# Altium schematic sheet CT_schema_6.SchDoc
size 266 x 267 mm
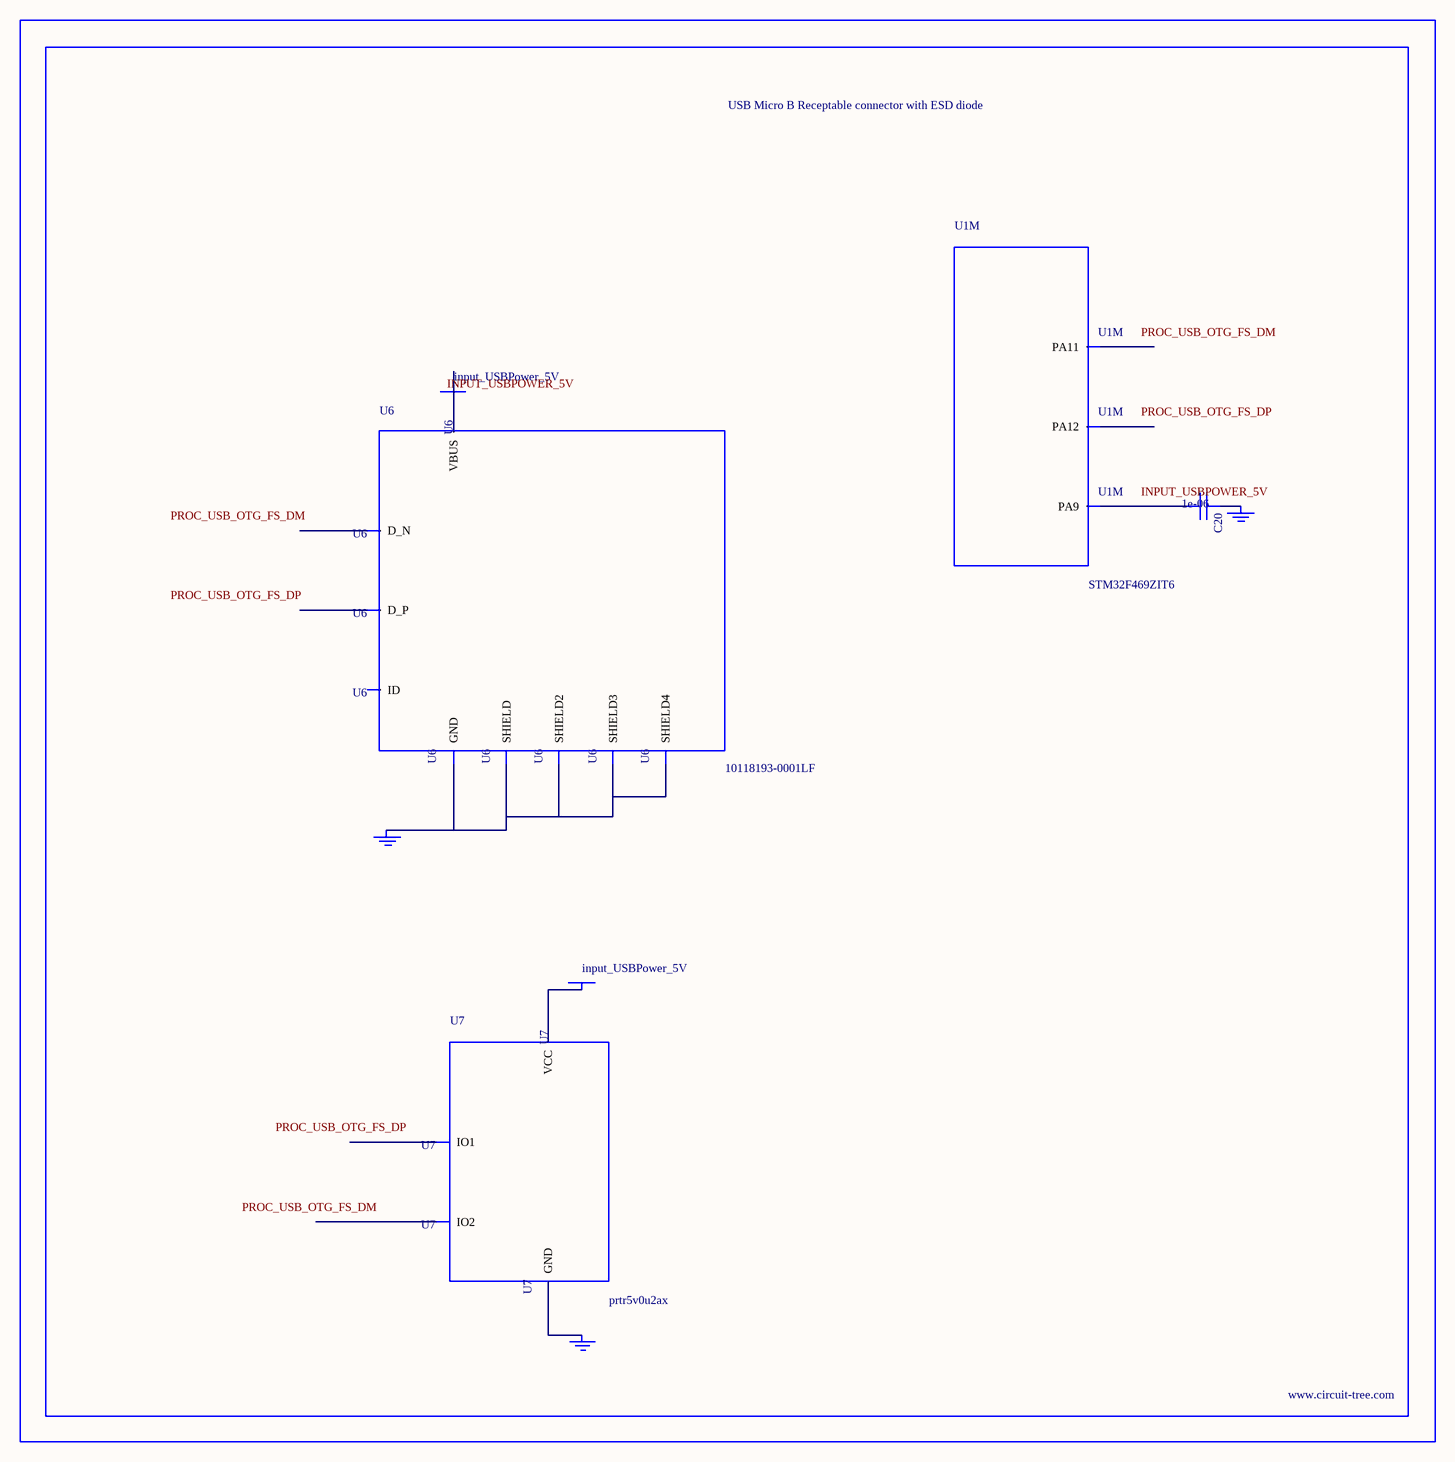
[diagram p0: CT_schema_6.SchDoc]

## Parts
BORDER5  (no value)
C20  1e-06  [C0603]
GND_INSTANCE_5_0  (no value)
GND_INSTANCE_5_1  (no value)
GND_INSTANCE_5_2  (no value)
POWER_INSTANCE_5_0  input_USBPower_5V
POWER_INSTANCE_5_1  input_USBPower_5V
U1  STM32F469ZIT6  [LQFP144]  (part M of 14)
U6  10118193-0001LF  [FCI_10118193-0001LF]
U7  prtr5v0u2ax  [SOT143B]

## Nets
NetC20_1: C20.1 GND_INSTANCE_5_1.0(GND)
NetC20_2: C20.2 U1.103(PA9)
NetGND_INSTANCE_5_0_0: GND_INSTANCE_5_0.0(GND) U6.5(GND) U6.6(SHIELD) U6.7(SHIELD2) U6.8(SHIELD3) U6.9(SHIELD4)
NetGND_INSTANCE_5_2_0: GND_INSTANCE_5_2.0(GND) U7.1(GND)
NetPOWER_INSTANCE_5_0_0: POWER_INSTANCE_5_0.0(PWR) U6.1(VBUS)
NetPOWER_INSTANCE_5_1_0: POWER_INSTANCE_5_1.0(PWR) U7.4(VCC)

Not connected (* = marked no-connect by the designer): U1 105(PA11) 106(PA12); U6 2(D_N) 3(D_P) 4(ID); U7 2(IO1) 3(IO2)

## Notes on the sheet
- Labels drawn without touching a wire or pin: INPUT_USBPOWER_5V, PROC_USB_OTG_FS_DM, PROC_USB_OTG_FS_DP

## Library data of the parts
BORDER5 = BORDER_PAGE5
C20 = C0603C105K3RACTU
GND_INSTANCE_5_0-GND_INSTANCE_5_2 = GND
POWER_INSTANCE_5_0 POWER_INSTANCE_5_1 = PWR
